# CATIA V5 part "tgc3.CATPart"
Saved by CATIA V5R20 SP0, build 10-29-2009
Part number: TGC3
Revision: 15
Definition: part definition
Nomenclature: TGC3
Source: Unknown
Description: NOT SPECIFIED
Bounding box of the stored display mesh (mm): x -3.1 to 26.9, y -6 to 6, z -22 to 5
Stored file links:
  C:\Users\Utente\Desktop\IO LAVORO\3D X SITO CF\X SITO\PLASTICA\TGC-XS\tgc3.CATPart
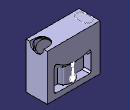
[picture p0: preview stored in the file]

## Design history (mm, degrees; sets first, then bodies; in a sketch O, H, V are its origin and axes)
Set1
  Line1 "LINE #7383": stored without definition
  DatumCurve1 "COMPOSITE_CURVE #7756"
  DatumCurve2 "COMPOSITE_CURVE #7948"
  DatumCurve3 "COMPOSITE_CURVE #7987"
  DatumCurve4 "COMPOSITE_CURVE #8049"
  DatumCurve5 "COMPOSITE_CURVE #8110"
  DatumCurve6 "COMPOSITE_CURVE #8149"
  DatumCurve7 "COMPOSITE_CURVE #8294"
  DatumCurve8 "COMPOSITE_CURVE #8371"
  DatumCurve9 "COMPOSITE_CURVE #8448"
  DatumCurve10 "COMPOSITE_CURVE #8523"
  DatumCurve11 "COMPOSITE_CURVE #8562"
  Circle1 "COMPOSITE_CURVE #8570": stored without definition
  Circle2 "COMPOSITE_CURVE #8581": stored without definition
  Circle3 "COMPOSITE_CURVE #8592": stored without definition
  Circle4 "COMPOSITE_CURVE #8603": stored without definition
  Circle5 "COMPOSITE_CURVE #8614": stored without definition
  Circle6 "COMPOSITE_CURVE #8625": stored without definition
  Circle7 "COMPOSITE_CURVE #8636": stored without definition
  Circle8 "COMPOSITE_CURVE #8647": stored without definition
  DatumSurface1 "OPEN_SHELL #6893"
  DatumSurface2 "OPEN_SHELL #7132"
  DatumSurface3 "OPEN_SHELL #7251"
  DatumSurface4 "OPEN_SHELL #7369"
Body1 "MANIFOLD_SOLID_BREP #7370" (main body)
  Solid1: solid without history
